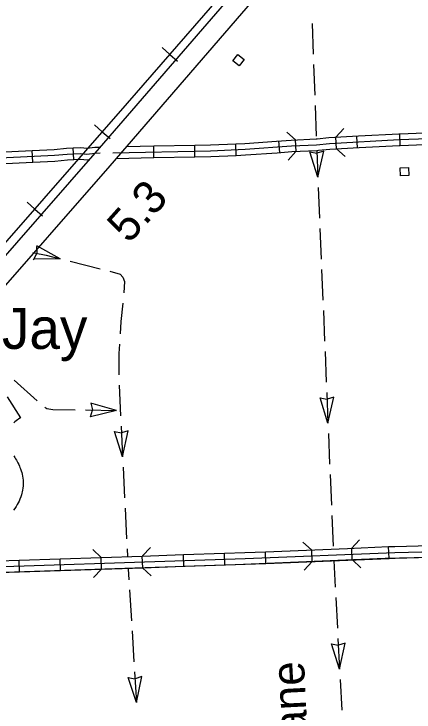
# Model space of a CAD drawing. Extents: x -0.3 to 2.65, y 0 to 1.9.
# Drawn here: x 0.5841 to 0.6457, y 0.3259 to 0.4334 of the extents above; entities that cross this region are included whole.
import ezdxf

# ---------------------------------------------------------------- set-up
doc = ezdxf.new("R2010")
doc.units = 0
for name, color, linetype in [('Level 12', 7, 'Continuous'), ('Level 15', 7, 'Continuous'), ('Level 16', 7, 'Continuous'), ('Level 19', 7, 'Continuous'), ('Level 24', 7, 'Continuous'), ('Level 26', 7, 'Continuous'), ('Level 27', 7, 'Continuous'), ('Level 28', 7, 'Continuous'), ('Level 29', 7, 'Continuous')]:
    doc.layers.add(name, color=color, linetype=linetype)

msp = doc.modelspace()

# ---------------------------------------------------------------- linework, layer by layer
at = {"layer": 'Level 12'}
for p, q in [((0.62965, 0.41221), (0.63072, 0.41197)), ((0.63088, 0.40829), (0.62965, 0.41221)), ((0.63178, 0.41229), (0.63073, 0.41197)), ((0.63088, 0.40829), (0.63178, 0.41229)), ((0.59125, 0.39572), (0.58766, 0.39771)), ((0.58759, 0.39764), (0.58766, 0.39655)), ((0.59125, 0.39572), (0.58715, 0.39565)), ((0.58717, 0.39556), (0.58766, 0.39654)), ((0.63121, 0.37433), (0.63227, 0.37409)), ((0.63243, 0.37041), (0.63121, 0.37433)), ((0.63333, 0.37442), (0.63229, 0.37409)), ((0.63243, 0.37041), (0.63333, 0.37442)), ((0.59594, 0.37351), (0.5962, 0.37245)), ((0.59989, 0.37238), (0.59594, 0.37351)), ((0.5959, 0.37139), (0.5962, 0.37244)), ((0.59989, 0.37238), (0.5959, 0.37139)), ((0.59959, 0.36916), (0.60066, 0.36893)), ((0.60084, 0.36525), (0.59959, 0.36916)), ((0.60171, 0.36926), (0.60067, 0.36893)), ((0.60084, 0.36525), (0.60171, 0.36926)), ((0.63295, 0.33645), (0.63402, 0.33622)), ((0.63423, 0.33254), (0.63295, 0.33645)), ((0.63507, 0.33656), (0.63403, 0.33622)), ((0.63423, 0.33254), (0.63507, 0.33656)), ((0.60168, 0.33129), (0.60275, 0.33108)), ((0.60298, 0.3274), (0.60168, 0.33129)), ((0.6038, 0.33142), (0.60276, 0.33108)), ((0.60298, 0.3274), (0.6038, 0.33142))]:
    msp.add_line(p, q, dxfattribs=at)
for points in [[(0.62999, 0.43196), (0.63016, 0.42723)], [(0.63022, 0.42565), (0.63039, 0.42091)], [(0.63045, 0.41933), (0.63062, 0.4146)], [(0.63071, 0.41242), (0.63088, 0.40829)], [(0.63094, 0.40671), (0.63114, 0.40197)], [(0.6312, 0.40039), (0.6314, 0.39566)], [(0.58704, 0.39668), (0.58724, 0.39663), (0.5891, 0.39626), (0.59125, 0.39572)], [(0.59278, 0.39534), (0.59738, 0.3942)], [(0.59891, 0.3938), (0.60048, 0.39336), (0.60091, 0.39292), (0.60115, 0.39225), (0.60111, 0.39138), (0.60102, 0.39047)], [(0.63146, 0.39408), (0.63165, 0.38935)], [(0.60087, 0.3889), (0.60058, 0.38605), (0.60047, 0.38418)], [(0.63172, 0.38777), (0.63191, 0.38303)], [(0.60038, 0.3826), (0.60029, 0.38115), (0.60027, 0.37787)], [(0.63198, 0.38146), (0.63217, 0.37672)], [(0.58418, 0.37706), (0.58769, 0.37387)], [(0.6003, 0.37629), (0.60054, 0.37156)], [(0.63224, 0.37514), (0.63243, 0.37041)], [(0.58889, 0.37286), (0.58918, 0.37268), (0.59013, 0.37255), (0.59357, 0.37249)], [(0.59515, 0.37246), (0.59989, 0.37238)], [(0.60061, 0.36998), (0.60084, 0.36525)], [(0.6325, 0.36883), (0.63269, 0.3641)], [(0.60092, 0.36367), (0.60115, 0.35894)], [(0.63276, 0.36252), (0.63295, 0.35778)], [(0.60123, 0.35736), (0.60146, 0.35262)], [(0.63302, 0.3562), (0.63321, 0.35147)], [(0.60154, 0.35105), (0.60159, 0.34989)], [(0.63331, 0.34926), (0.63354, 0.34516)], [(0.6017, 0.34801), (0.6018, 0.34632)], [(0.6019, 0.34474), (0.6022, 0.34001)], [(0.63362, 0.34358), (0.63388, 0.33885)], [(0.6023, 0.33843), (0.60259, 0.3337)], [(0.63397, 0.33727), (0.63423, 0.33254)], [(0.60269, 0.33213), (0.60298, 0.3274)], [(0.63431, 0.33097), (0.63457, 0.32623)]]:
    msp.add_lwpolyline(points, dxfattribs=at)
at = {"layer": 'Level 15'}
for p, q in [((0.64353, 0.41319), (0.64347, 0.41499)), ((0.62503, 0.41209), (0.6249, 0.41388)), ((0.62755, 0.41227), (0.62742, 0.41406)), ((0.63373, 0.41268), (0.63366, 0.41445)), ((0.63695, 0.41281), (0.63688, 0.41458)), ((0.59334, 0.411), (0.59326, 0.41279)), ((0.60566, 0.4113), (0.60563, 0.4131)), ((0.61198, 0.41143), (0.61194, 0.41322)), ((0.61832, 0.41165), (0.61824, 0.41344)), ((0.58704, 0.41061), (0.58695, 0.4124)), ((0.61657, 0.3486), (0.61651, 0.35039)), ((0.62289, 0.34883), (0.62281, 0.35063)), ((0.63, 0.34913), (0.62993, 0.35092)), ((0.63615, 0.34938), (0.63608, 0.35117)), ((0.64183, 0.34961), (0.64175, 0.35141)), ((0.58499, 0.34754), (0.58493, 0.34933)), ((0.59131, 0.34775), (0.59125, 0.34954)), ((0.59762, 0.34796), (0.59756, 0.34976)), ((0.60394, 0.34817), (0.60388, 0.34997)), ((0.61025, 0.34839), (0.61019, 0.35018))]:
    msp.add_line(p, q, dxfattribs=at)
for points in [[(0.59933, 0.41206), (0.61438, 0.41236), (0.61971, 0.41259), (0.6268, 0.4131), (0.63067, 0.41329), (0.63265, 0.4135), (0.64336, 0.41407), (0.69077, 0.41572), (0.69699, 0.41603)], [(0.63714, 0.41465), (0.64332, 0.41498), (0.64347, 0.41499)], [(0.64347, 0.41499), (0.64978, 0.41521)], [(0.61824, 0.41344), (0.61966, 0.4135), (0.62452, 0.41385)], [(0.62452, 0.41385), (0.62675, 0.41401), (0.6306, 0.4142), (0.63079, 0.41422)], [(0.63079, 0.41422), (0.63258, 0.41441), (0.63714, 0.41465)], [(0.58695, 0.4124), (0.59032, 0.41257), (0.59224, 0.41275), (0.59326, 0.41279)], [(0.59326, 0.41279), (0.59441, 0.41284), (0.59535, 0.41278), (0.59657, 0.41292), (0.59743, 0.41293)], [(0.60146, 0.41301), (0.60563, 0.4131)], [(0.60563, 0.4131), (0.61194, 0.41322)], [(0.61194, 0.41322), (0.61435, 0.41327), (0.61824, 0.41344)], [(0.63098, 0.41244), (0.63272, 0.41262), (0.63724, 0.41286)], [(0.63724, 0.41286), (0.6434, 0.41319), (0.64353, 0.41319)], [(0.64353, 0.41319), (0.64984, 0.41341)], [(0.49976, 0.40945), (0.50336, 0.40956), (0.50367, 0.40949), (0.50387, 0.40932), (0.504, 0.40911), (0.50426, 0.40808), (0.50448, 0.40785), (0.50486, 0.40769), (0.50554, 0.40765), (0.52019, 0.40826), (0.59039, 0.41166), (0.59231, 0.41184), (0.5944, 0.41193), (0.59537, 0.41186), (0.59663, 0.412)], [(0.58064, 0.4121), (0.58695, 0.4124)], [(0.59663, 0.412), (0.59739, 0.41202)], [(0.61198, 0.41143), (0.61441, 0.41148), (0.61832, 0.41165)], [(0.61832, 0.41165), (0.61976, 0.41171), (0.62464, 0.41206)], [(0.62464, 0.41206), (0.62685, 0.41222), (0.63074, 0.41241), (0.63098, 0.41244)], [(0.58073, 0.41031), (0.58704, 0.41061)], [(0.58704, 0.41061), (0.59045, 0.41078), (0.59237, 0.41096), (0.59334, 0.411)], [(0.59334, 0.411), (0.59439, 0.41105), (0.59539, 0.41098), (0.59577, 0.41102)], [(0.59988, 0.41119), (0.60566, 0.4113)], [(0.60566, 0.4113), (0.61198, 0.41143)], [(0.5393, 0.34569), (0.53962, 0.34567), (0.5687, 0.34702), (0.6182, 0.34868), (0.64125, 0.34962), (0.67238, 0.35037), (0.68621, 0.35084), (0.7223, 0.35242), (0.72331, 0.35266), (0.72461, 0.35251), (0.75509, 0.35425), (0.78917, 0.35598), (0.80036, 0.35662), (0.80108, 0.35675), (0.80142, 0.35688), (0.80169, 0.35716), (0.80183, 0.35762), (0.80186, 0.35821), (0.8016, 0.36326)], [(0.54078, 0.3466), (0.54109, 0.34658), (0.57017, 0.34792), (0.61968, 0.34958), (0.64273, 0.35053), (0.67386, 0.35128), (0.68769, 0.35175), (0.72378, 0.35333), (0.72478, 0.35357), (0.72608, 0.35342), (0.75657, 0.35515), (0.79065, 0.35689), (0.80184, 0.35753), (0.80255, 0.35766), (0.80289, 0.35779), (0.80317, 0.35807), (0.80331, 0.35853), (0.80334, 0.35912), (0.80308, 0.36417)], [(0.64175, 0.35141), (0.6427, 0.35144), (0.64808, 0.35157)], [(0.61019, 0.35018), (0.61651, 0.35039)], [(0.61651, 0.35039), (0.61964, 0.3505), (0.62281, 0.35063)], [(0.62281, 0.35063), (0.62913, 0.35089)], [(0.62913, 0.35089), (0.63544, 0.35115)], [(0.63544, 0.35115), (0.64175, 0.35141)], [(0.57862, 0.34912), (0.58493, 0.34933)], [(0.58493, 0.34933), (0.59125, 0.34954)], [(0.59125, 0.34954), (0.59756, 0.34976)], [(0.59756, 0.34976), (0.60388, 0.34997)], [(0.60388, 0.34997), (0.61019, 0.35018)], [(0.6292, 0.34909), (0.63551, 0.34935)], [(0.63551, 0.34935), (0.64183, 0.34961)], [(0.64183, 0.34961), (0.64276, 0.34965), (0.64813, 0.34978)], [(0.60394, 0.34817), (0.61025, 0.34839)], [(0.61025, 0.34839), (0.61657, 0.3486)], [(0.61657, 0.3486), (0.61971, 0.3487), (0.62289, 0.34883)], [(0.62289, 0.34883), (0.6292, 0.34909)], [(0.57868, 0.34733), (0.58499, 0.34754)], [(0.58499, 0.34754), (0.59131, 0.34775)], [(0.59131, 0.34775), (0.59762, 0.34796)], [(0.59762, 0.34796), (0.60394, 0.34817)]]:
    msp.add_lwpolyline(points, dxfattribs=at)
at = {"layer": 'Level 19'}
for points in [[(0.61876, 0.42542), (0.61779, 0.4262), (0.61856, 0.42718), (0.61954, 0.4264)], [(0.64361, 0.40848), (0.64355, 0.40973), (0.6448, 0.40978), (0.64486, 0.40854)]]:
    msp.add_lwpolyline(points, close=True, dxfattribs=at)
at = {"layer": 'Level 26'}
for points in [[(0.5831, 0.37446), (0.58517, 0.37125), (0.58503, 0.37117), (0.58485, 0.37105), (0.58468, 0.37093), (0.58446, 0.37076), (0.58428, 0.37061), (0.58412, 0.37046)], [(0.58411, 0.36538), (0.58426, 0.36516), (0.5844, 0.36493), (0.58452, 0.36473), (0.58463, 0.36454), (0.58474, 0.36432), (0.58487, 0.36406), (0.58498, 0.3638), (0.58506, 0.36361), (0.58515, 0.36337), (0.58525, 0.36307), (0.58533, 0.36282), (0.58541, 0.36255), (0.58548, 0.36224), (0.58552, 0.36196), (0.58555, 0.36167), (0.58557, 0.36135), (0.58558, 0.36105), (0.58556, 0.36076), (0.58553, 0.36041), (0.58547, 0.36009), (0.58542, 0.35984), (0.58536, 0.35962), (0.58529, 0.35938), (0.5852, 0.35907), (0.58506, 0.35871), (0.58494, 0.35843), (0.58481, 0.35816), (0.58466, 0.35788), (0.58446, 0.35757), (0.58426, 0.35728), (0.58406, 0.35703)]]:
    msp.add_lwpolyline(points, dxfattribs=at)
at = {"layer": 'Level 27'}
for points in [[(0.53986, 0.34704), (0.59663, 0.412), (0.62311, 0.44268)], [(0.62536, 0.44071), (0.59889, 0.41004), (0.54211, 0.34507)]]:
    msp.add_lwpolyline(points, dxfattribs=at)
at = {"layer": 'Level 28'}
for p, q in [((0.6081, 0.4272), (0.60691, 0.42824)), ((0.6081, 0.4272), (0.60929, 0.42617)), ((0.59773, 0.41529), (0.59654, 0.41633)), ((0.59773, 0.41529), (0.59892, 0.41425)), ((0.58734, 0.40339), (0.58615, 0.40443)), ((0.58734, 0.40339), (0.58853, 0.40235))]:
    msp.add_line(p, q, dxfattribs=at)
for points in [[(0.50451, 0.30855), (0.53786, 0.34671), (0.60158, 0.41969), (0.64921, 0.4745), (0.6908, 0.52224), (0.7076, 0.54164)], [(0.50451, 0.30855), (0.53786, 0.34671), (0.60158, 0.41969), (0.64921, 0.4745), (0.6908, 0.52224), (0.7076, 0.54164)], [(0.50451, 0.30855), (0.53786, 0.34671), (0.60158, 0.41969), (0.64921, 0.4745), (0.6908, 0.52224), (0.7076, 0.54164)], [(0.50451, 0.30855), (0.53786, 0.34671), (0.60158, 0.41969), (0.64921, 0.4745), (0.6908, 0.52224), (0.7076, 0.54164)], [(0.40386, 0.14427), (0.4188, 0.17053), (0.43403, 0.19722), (0.4497, 0.22484), (0.4732, 0.266), (0.47682, 0.27303), (0.47817, 0.27549), (0.4797, 0.2782), (0.48111, 0.28039), (0.48332, 0.28357), (0.48511, 0.28592), (0.48761, 0.28907), (0.49328, 0.29577), (0.49996, 0.30333), (0.50451, 0.30855), (0.53786, 0.34671), (0.60158, 0.41969), (0.64921, 0.4745), (0.68992, 0.52123)]]:
    msp.add_lwpolyline(points, dxfattribs=at)
at = {"layer": 'Level 29'}
for points in [[(0.62609, 0.41523), (0.62742, 0.41403)], [(0.63366, 0.41445), (0.63486, 0.41579)], [(0.62751, 0.41223), (0.62631, 0.4109)], [(0.63509, 0.41146), (0.63376, 0.41266)], [(0.62859, 0.35212), (0.62991, 0.3509)], [(0.63606, 0.35115), (0.63728, 0.35248)], [(0.59625, 0.35097), (0.59756, 0.34975)], [(0.60389, 0.34998), (0.60512, 0.35129)], [(0.63751, 0.34815), (0.63619, 0.34936)], [(0.62998, 0.34911), (0.62876, 0.34779)], [(0.59762, 0.34795), (0.59639, 0.34664)], [(0.60524, 0.34694), (0.60393, 0.34816)]]:
    msp.add_lwpolyline(points, dxfattribs=at)

# ---------------------------------------------------------------- texts
at = {"layer": 'Level 12'}
msp.add_text('Hurricane', height=0.005055, rotation=92.8846, dxfattribs=at).set_placement((0.6302, 0.30459))
at = {"layer": 'Level 16'}
msp.add_text('5.3', height=0.005055, rotation=48.2921, dxfattribs=at).set_placement((0.60182, 0.39794))
at = {"layer": 'Level 24'}
msp.add_text('Jay', height=0.006318, dxfattribs=at).set_placement((0.58229, 0.38185))

doc.saveas('drawing.dxf')
